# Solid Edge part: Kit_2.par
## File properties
Sűrűség: 0,000 kg/m^3
Pontosság: 0,990
Author: bmolnar
Last saved by: bmolnar
Revision: 76
Username: bmolnar
Dokumentum tartalom típus: 0
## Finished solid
Body 1: solid body, 20 faces, 36 edges, 26 vertices.
  Faces by surface: cylinder 10, plane 9, cone 1
  Edges by curve: circle 22, line 14
Bounding box of the edges (mm): 85.500 x 85.350 x 6.900, from (-42.75, -40.85, 0.95) to (42.75, 44.5, 7.85).
Cylindrical faces by radius (mm): R1.5 x2, R3 x4, R31 x1, R37.5 x1, R40.85 x1, R42.75 x1
Conical faces (half-angle, radius in mm at the cone's reference point): 45 deg R30.5 x1
Planar faces by outward normal: +z 2, -z 5, oblique 2
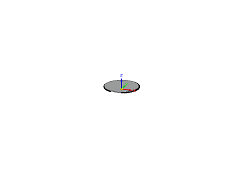
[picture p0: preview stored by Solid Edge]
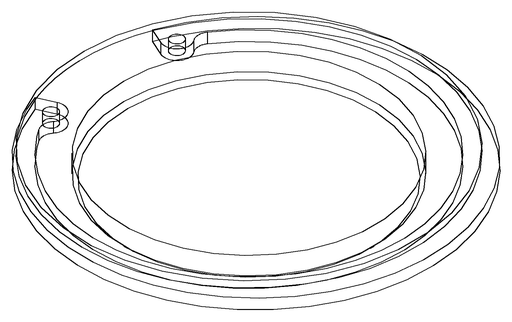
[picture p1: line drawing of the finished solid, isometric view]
